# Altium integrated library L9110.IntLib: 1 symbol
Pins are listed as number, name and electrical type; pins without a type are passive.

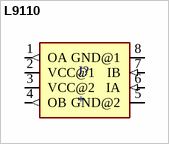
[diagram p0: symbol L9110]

## L9110
designator J?
Motor control driver chip; MF: Asic; MP: L9110 (SOP-8)
footprint SO-08
pins: 1 OA (out), 2 VCC@1 (power), 3 VCC@2 (power), 4 OB (out), 5 GND@2 (power), 6 IA (in), 7 IB (in), 8 GND@1 (power)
